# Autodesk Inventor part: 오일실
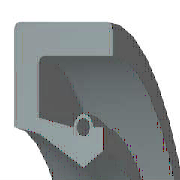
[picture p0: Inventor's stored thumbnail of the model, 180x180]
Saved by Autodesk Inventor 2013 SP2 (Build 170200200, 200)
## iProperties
IsCustomPart: 1
Created: 2009-02
Part Number: 오일실
Material: 고무
Description: 오일-실
Document SubType Name: Modeling
Standard: KS B 2804
Designer: SeoGD™[esajin.kr]
Standards Organization: KS
Language: ko-KR
Size Designation: S - 25 38 8
Categories: <MemberInstance><Categories><Category DisplayName="샤프트 부품" InternalName="7f7aeb1f-a693-4053-b835-cee3144e0d98" Mnemonic="SHFT"><Category DisplayName="실링" Intern
Density: 0.93 g/cm^3
Mass: 2.23721 g
Surface Area: 37.0166 cm^2
Volume: 2.4056 cm^3
Author: SeoGD™[esajin.kr]
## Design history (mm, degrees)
revolve "본체" stored, may be unused: angle "d17" = 90 deg
revolve "스프링1" stored, may be unused: angle "d18" = 90 deg
body "Solid1"
sketch "스케치1"
  geometry: L1 (0, 19)-(8, 19); L2 (8, 19)-(8, 17.75); L3 (8, 17.75)-(1.75, 17.75); L4 (0, 19)-(0, 14.6); L5 (0, 14.6)-(1.75, 14.25); L6 (1.75, 14.25)-(4.9, 12.5); L7 (4.9, 12.5)-(0, 12.5); L8 (6.3, 13.375)-(6.3, 14.6); L9 (0, 0)-(9.586, 0) reference; L10 (4.9, 12.5)-(6.3, 13.375); L11 (0, 18)-(0, -3) reference; L12 (-1.917, 0)-(11.503, 0) reference; L13 (4.2, 14.6)-(1.75, 15.09); L14 (1.75, 15.09)-(1.75, 17.75); L15 (6.3, 14.6)-(5.6, 14.6); C1 r 0.455 at (4.9, 14.6); A1 r 0.7 centre (4.9, 14.6) between (5.6, 14.6) and (4.2, 14.6)
  constraints: 26 end point, 5 horizontal alignment, 4 perpendicular, 2 centre point, 2 collinear, 2 horizontal, 2 parallel, 2 point on circle, 2 point on line, 2 vertical alignment, 1 coincident
  dimensions: "d0" = 38 diameter of L1 L9 (= SD2); "d1" = 26.75 diameter of L8.start L9 (= ABDM); "d2" = 1.25 distance of L1.end L2.end (computed from SD); "d3" = 0.91 diameter of C1 (= SPDI); "d4" = 1.4 diameter of A1 (= SPDA); "d5" = 25 diameter of L6.end L9 (= NND); "d6" = 28.5 diameter of L5.end L9 (= TKDM); "d7" = 29.2 diameter of L4.end L9 (= HLDM); "d8" = 4.9 distance from line of C1.centre L4 (= SPDST); "d9" = 6.3 distance between parallel lines of L8 L4 (= SDI); "d10" = 8 distance between parallel lines of L2 L4 (= SWDT); "d12" = 1.75 distance between parallel lines of L14 L4 (= SD)
fillet "모깎기1" dims "d11" = 0.3 (= RR)
other parameters: "SD2" = 38 [user parameter; used in 1 equation term], "SWDT" = 8 [user parameter; used in 1 equation term], "RR" = 0.3 [user parameter; used in 1 equation term], "SD" = 1.75 [user parameter; used in 2 equation terms], "NND" = 25 [user parameter; used in 1 equation term], "SPDA" = 1.4 [user parameter; used in 1 equation term], "SPDI" = 0.91 [user parameter; used in 1 equation term], "TKDM" = 28.5 [user parameter; used in 1 equation term], "HLDM" = 29.2 [user parameter; used in 1 equation term], "ABDM" = 26.75 [user parameter; used in 1 equation term], "SDI" = 6.3 [user parameter; used in 1 equation term], "SPDST" = 4.9 [user parameter; used in 1 equation term], "d13" = 0, "d14" = 0, "d15" = 0, "LAB" = 0.35 [user parameter]
